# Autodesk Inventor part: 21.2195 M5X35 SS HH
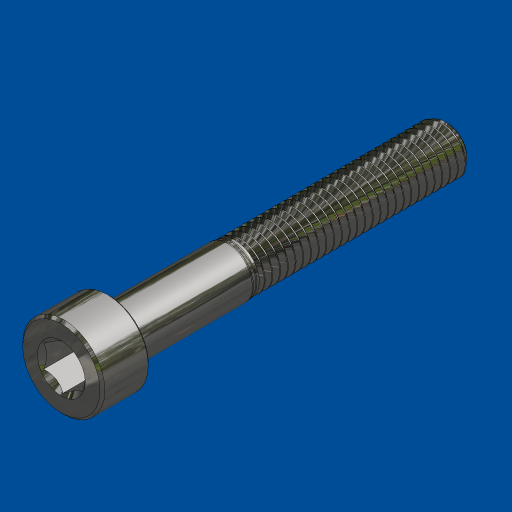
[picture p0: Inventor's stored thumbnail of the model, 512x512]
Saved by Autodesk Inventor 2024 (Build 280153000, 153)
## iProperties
Company: Managed by Terraform
Created: 2023-01
Part Number: 21.2195 M5X35 SS HH
Material: Stainless Steel
Description: STEP AP203
Document SubType Name: Modeling
Designer: amoles
Appearance: Stainless - Brushed
Mass: 6.77726 g
Surface Area: 10.3416 cm^2
Volume: 0.847157 cm^3
Density: 8 g/cm^3
Sending System: SolidWorks 2017
Preprocessor: SwSTEP 2.0
Title: 91290A256_Alloy Steel Socket Head Screw.STEP
Author: Administrator
Revision Number: ANY
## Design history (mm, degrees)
feature "Revolve2"
body "Solid1"
